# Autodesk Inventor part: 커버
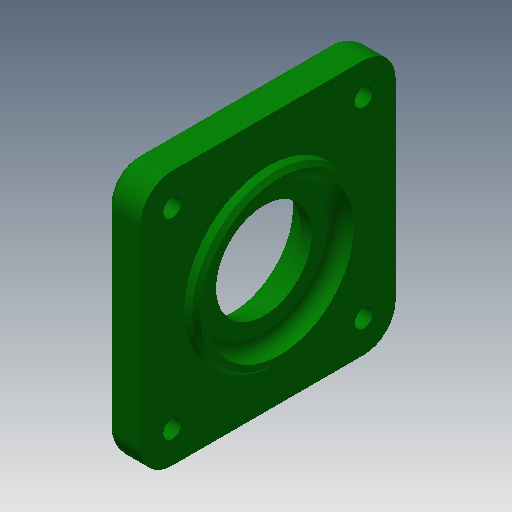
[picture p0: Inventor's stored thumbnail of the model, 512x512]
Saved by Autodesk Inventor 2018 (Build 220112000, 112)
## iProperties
Created: 2019-09
Part Number: 커버
Material: 알루미늄 6061
Document SubType Name: Modeling
Designer: mduedu
Density: 1 g/cm^3
Appearance: 진녹색
Author: mduedu
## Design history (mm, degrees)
sketch "스케치1"
  geometry: L1 (-32, -32)-(32, -32); L2 (32, -32)-(32, 32); L3 (32, 32)-(-32, 32); L4 (-32, 32)-(-32, -32); L5 (-32, -32)-(32, 32); L6 (32, -32)-(-32, 32); 1 further point
  constraints: 12 end point, 2 midpoint, 2 parallel, 1 horizontal, 1 perpendicular
  dimensions: "d44" = 64 distance of L3.end L2.end; "d45" = 64 distance of L2.end L1.end
extrude "돌출1" new body sketch "스케치1" distance "d1" = 9; taper "d2" = 0 deg
sketch "스케치2"
  geometry: C1 r 21 at (0, 0); 1 further point
  constraints: 1 centre point, 1 coincident
  dimensions: "d3" = 42 diameter of C1
extrude "돌출2" join sketch "스케치2" distance "d4" = 3; taper "d5" = 0 deg
hole "구멍1" diameter "d8" = 24; stored, may be unused: countersink angle "d12" = 90 deg, drill point angle "d14" = 118 deg; dims "d9" = 6, "d10" = 30, "d11" = 5.2, "d13" = 8, "d46" = 10, "d47" = 10
hole "구멍2" diameter "d17" = 37; stored, may be unused: countersink angle "d21" = 90 deg, drill point angle "d23" = 0 deg; dims "d15" = 10, "d16" = 10, "d18" = 6, "d19" = 30, "d20" = 5.2, "d22" = 4
fillet "모깎기1" dims "d24" = 3
fillet "모깎기4" dims "d48" = 8
fillet "모깎기2" dims "d25" = 3
chamfer "모따기1" distance "d27" = 0.5; stored, may be unused: second distance "d28" = 2, angle "d29" = 30 deg
chamfer "모따기2" distance "d30" = 1; stored, may be unused: second distance "d31" = 2, angle "d32" = 30 deg
sketch "스케치4"
  geometry: A1 r 8 centre (-24, 24) between (-24, 32) and (-32, 24) reference; A2 r 8 centre (24, 24) between (32, 24) and (24, 32) reference; A3 r 8 centre (24, -24) between (24, -32) and (32, -24) reference; A4 r 8 centre (-24, -24) between (-32, -24) and (-24, -32) reference; 5 further points
  constraints: 4 coincident
hole "구멍4" sketch "스케치4" at (-24, 24), (24, 24), (24, -24), (-24, -24) diameter "d49" = 4.5; stored, may be unused: countersink angle "d53" = 90 deg, drill point angle "d55" = 118 deg; dims "d50" = 6, "d51" = 8, "d52" = 4.4, "d54" = 8
node "솔리드1"
